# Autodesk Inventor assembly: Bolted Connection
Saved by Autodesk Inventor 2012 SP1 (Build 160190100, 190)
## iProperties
Created: 2006-09
Part Number: Bolted Connection
Document SubType Name: Assembly
ClientObjectVersion: 1
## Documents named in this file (3)
- D:\Backup\CMU Work Temp\XX\Inv2012DynSim\Sub-Assemblies\Bolted Connection7.iam
- D:\Backup\CMU Work Temp\XX\Inv2012DynSim\Parts\M5-16.ipt
- D:\Backup\CMU Work Temp\XX\Inv2012DynSim\Parts\M5.ipt
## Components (2 placed, 2 different names)
1. Indented Hex Head Machine Screw - Metric M5 x 0.8 x 16:1
2. DIN 6923 M5:1
